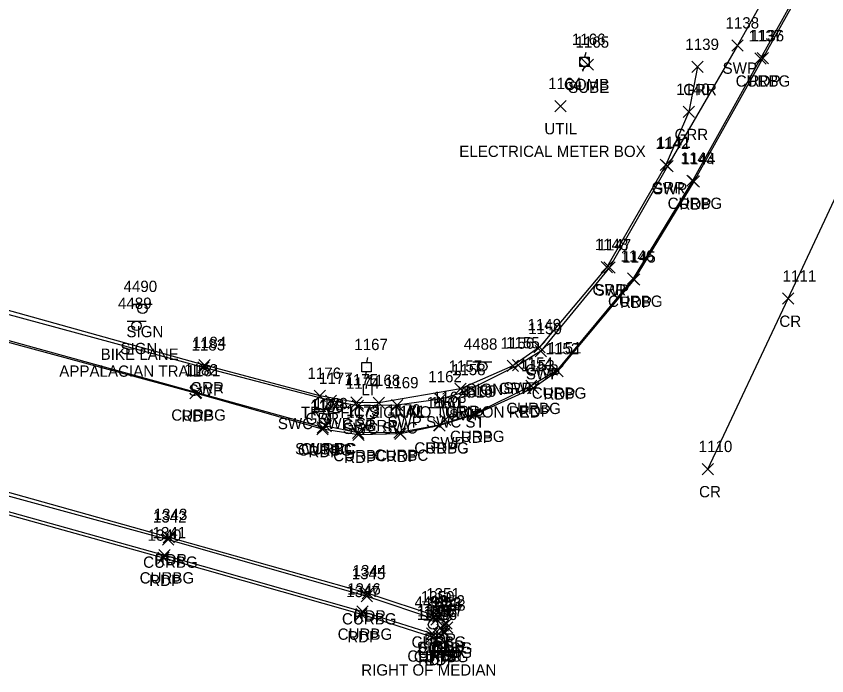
# Model space of a CAD drawing. Extents: x 1690689 to 1696275, y 438760 to 444007.
# Drawn here: x 1692953 to 1693096.4, y 438844.6 to 438961.2 of the extents above; entities that cross this region are included whole.
import ezdxf

# ---------------------------------------------------------------- set-up
doc = ezdxf.new("R2010")
doc.units = 0
for name, color, linetype in [('P_A', 7, 'Continuous'), ('P_I', 7, 'Continuous'), ('P_TIC', 7, 'Continuous'), ('PET', 7, 'Continuous'), ('PRC', 7, 'Continuous'), ('R_A', 7, 'Continuous'), ('R_I', 7, 'Continuous'), ('R_TIC', 7, 'Continuous'), ('RC', 7, 'Continuous'), ('RGR', 7, 'Continuous'), ('RSW', 7, 'Continuous'), ('S_A', 7, 'Continuous'), ('S_C', 7, 'Continuous'), ('S_I', 7, 'Continuous'), ('SSGN', 7, 'Continuous'), ('U_A', 7, 'Continuous'), ('U_C', 7, 'Continuous'), ('U_I', 7, 'Continuous'), ('U_TIC', 7, 'Continuous'), ('UDEFAULT', 7, 'Continuous'), ('ULP', 7, 'Continuous'), ('UP', 7, 'Continuous')]:
    doc.layers.add(name, color=color, linetype=linetype)

msp = doc.modelspace()

# ---------------------------------------------------------------- linework, layer by layer
at = {"layer": 'P_TIC'}
for points in [[(1693084.1, 438952.79), (1693086.1, 438954.79)], [(1693086.1, 438952.79), (1693084.1, 438954.79)], [(1693071.88, 438931.02), (1693073.88, 438933.02)], [(1693073.88, 438931.02), (1693071.88, 438933.02)], [(1693061.34, 438913.66), (1693063.34, 438915.66)], [(1693063.34, 438913.66), (1693061.34, 438915.66)], [(1693088.6, 438910.3), (1693090.6, 438912.3)], [(1693090.6, 438910.3), (1693088.6, 438912.3)], [(1693047.8, 438897.45), (1693049.8, 438899.45)], [(1693049.8, 438897.45), (1693047.8, 438899.45)], [(1693043.46, 438894.45), (1693045.46, 438896.45)], [(1693045.46, 438894.45), (1693043.46, 438896.45)], [(1692983.73, 438893.57), (1692985.73, 438895.57)], [(1692985.73, 438893.57), (1692983.73, 438895.57)], [(1693033.2, 438889.8), (1693035.2, 438891.8)], [(1693035.2, 438889.8), (1693033.2, 438891.8)], [(1693006.21, 438887.24), (1693008.21, 438889.24)], [(1693008.21, 438887.24), (1693006.21, 438889.24)], [(1693026.9, 438887.88), (1693028.9, 438889.88)], [(1693028.9, 438887.88), (1693026.9, 438889.88)], [(1693012.55, 438886.23), (1693014.55, 438888.23)], [(1693014.55, 438886.23), (1693012.55, 438888.23)], [(1693019.98, 438886.4), (1693021.98, 438888.4)], [(1693021.98, 438886.4), (1693019.98, 438888.4)], [(1693074.4, 438880.17), (1693076.4, 438882.17)], [(1693076.4, 438880.17), (1693074.4, 438882.17)], [(1692979.03, 438868.15), (1692981.03, 438870.15)], [(1692981.03, 438868.15), (1692979.03, 438870.15)], [(1692978.05, 438864.49), (1692980.05, 438866.49)], [(1692980.05, 438864.49), (1692978.05, 438866.49)], [(1693014.23, 438858.21), (1693016.23, 438860.21)], [(1693016.23, 438858.21), (1693014.23, 438860.21)], [(1693013.1, 438854.52), (1693015.1, 438856.52)], [(1693015.1, 438854.52), (1693013.1, 438856.52)], [(1693026.67, 438854.11), (1693028.67, 438856.11)], [(1693028.67, 438854.11), (1693026.67, 438856.11)], [(1693028.13, 438852.87), (1693030.13, 438854.87)], [(1693030.13, 438852.87), (1693028.13, 438854.87)], [(1693028.26, 438852.13), (1693030.26, 438854.13)], [(1693030.26, 438852.13), (1693028.26, 438854.13)], [(1693028.26, 438852.13), (1693030.26, 438854.13)], [(1693030.26, 438852.13), (1693028.26, 438854.13)], [(1693027.79, 438851.15), (1693029.79, 438853.15)], [(1693029.79, 438851.15), (1693027.79, 438853.15)], [(1693025.61, 438850.49), (1693027.61, 438852.49)], [(1693027.61, 438850.49), (1693025.61, 438852.49)], [(1693026.81, 438850.47), (1693028.81, 438852.47)], [(1693028.81, 438850.47), (1693026.81, 438852.47)]]:
    msp.add_lwpolyline(points, dxfattribs=at)
at = {"layer": 'PET'}
for points in [[(1693125.8, 439077.7), (1693116.74, 439032.37), (1693117.43, 439025.65), (1693115.9, 439015.71), (1693111.21, 439002.42), (1693106.01, 438991.1), (1693085.1, 438953.79), (1693072.88, 438932.02), (1693062.34, 438914.66), (1693048.8, 438898.45), (1693044.46, 438895.45), (1693034.2, 438890.8), (1693027.9, 438888.88), (1693020.98, 438887.4), (1693013.55, 438887.23), (1693007.21, 438888.24), (1692984.73, 438894.57), (1692943.33, 438905.8), (1692898.33, 438918.08), (1692858.37, 438928.85), (1692835.39, 438935.21), (1692797.06, 438945.81)], [(1692767.64, 438925.55), (1692788.12, 438920.87), (1692810.81, 438915.2), (1692847.49, 438905.73), (1692889.57, 438894.03), (1692933.46, 438882.17), (1692980.03, 438869.15), (1693015.23, 438859.21), (1693027.67, 438855.11), (1693029.13, 438853.87), (1693029.26, 438853.13)], [(1692765.95, 438921.86), (1692787.57, 438917.51), (1692810.13, 438912.04), (1692846.3, 438902.13), (1692888.63, 438890.39), (1692931.95, 438878.57), (1692979.05, 438865.49), (1693014.1, 438855.52), (1693026.61, 438851.49), (1693027.81, 438851.47), (1693028.79, 438852.15), (1693029.26, 438853.13)]]:
    msp.add_lwpolyline(points, dxfattribs=at)
at = {"layer": 'PRC'}
msp.add_lwpolyline([(1693075.4, 438881.17), (1693089.6, 438911.3), (1693103.78, 438941.64), (1693117.42, 438973.77), (1693128.92, 439005.9), (1693137.63, 439039.04), (1693143.37, 439073.85)], dxfattribs=at)
at = {"layer": 'R_TIC'}
for points in [[(1693079.63, 438955.05), (1693081.63, 438957.05)], [(1693081.63, 438955.05), (1693079.63, 438957.05)], [(1693083.72, 438952.77), (1693085.72, 438954.77)], [(1693085.72, 438952.77), (1693083.72, 438954.77)], [(1693072.53, 438951.26), (1693074.53, 438953.26)], [(1693074.53, 438951.26), (1693072.53, 438953.26)], [(1693071, 438943.32), (1693073, 438945.32)], [(1693073, 438943.32), (1693071, 438945.32)], [(1693066.94, 438933.93), (1693068.94, 438935.93)], [(1693068.94, 438933.93), (1693066.94, 438935.93)], [(1693067.27, 438933.74), (1693069.27, 438935.74)], [(1693069.27, 438933.74), (1693067.27, 438935.74)], [(1693071.69, 438931.15), (1693073.69, 438933.15)], [(1693073.69, 438931.15), (1693071.69, 438933.15)], [(1693056.5, 438915.87), (1693058.5, 438917.87)], [(1693058.5, 438915.87), (1693056.5, 438917.87)], [(1693057, 438915.81), (1693059, 438917.81)], [(1693059, 438915.81), (1693057, 438917.81)], [(1693061.14, 438913.84), (1693063.14, 438915.84)], [(1693063.14, 438913.84), (1693061.14, 438915.84)], [(1693044.6, 438901.71), (1693046.6, 438903.71)], [(1693046.6, 438901.71), (1693044.6, 438903.71)], [(1693044.81, 438901.02), (1693046.81, 438903.02)], [(1693046.81, 438901.02), (1693044.81, 438903.02)], [(1692985.15, 438898.12), (1692987.15, 438900.12)], [(1692987.15, 438898.12), (1692985.15, 438900.12)], [(1692985.35, 438898.55), (1692987.35, 438900.55)], [(1692987.35, 438898.55), (1692985.35, 438900.55)], [(1693039.89, 438898.43), (1693041.89, 438900.43)], [(1693041.89, 438898.43), (1693039.89, 438900.43)], [(1693040.81, 438898.51), (1693042.81, 438900.51)], [(1693042.81, 438898.51), (1693040.81, 438900.51)], [(1693047.64, 438897.6), (1693049.64, 438899.6)], [(1693049.64, 438897.6), (1693047.64, 438899.6)], [(1692983.87, 438893.72), (1692985.87, 438895.72)], [(1692985.87, 438893.72), (1692983.87, 438895.72)], [(1693030.63, 438894.36), (1693032.63, 438896.36)], [(1693032.63, 438894.36), (1693030.63, 438896.36)], [(1693031.24, 438893.76), (1693033.24, 438895.76)], [(1693033.24, 438893.76), (1693031.24, 438895.76)], [(1693043.15, 438894.89), (1693045.15, 438896.89)], [(1693045.15, 438894.89), (1693043.15, 438896.89)], [(1693005.72, 438893.11), (1693007.72, 438895.11)], [(1693007.72, 438893.11), (1693005.72, 438895.11)], [(1693007.71, 438892.22), (1693009.71, 438894.22)], [(1693009.71, 438892.22), (1693007.71, 438894.22)], [(1693007.71, 438892.22), (1693009.71, 438894.22)], [(1693009.71, 438892.22), (1693007.71, 438894.22)], [(1693027.09, 438892.51), (1693029.09, 438894.51)], [(1693029.09, 438892.51), (1693027.09, 438894.51)], [(1693027.09, 438892.51), (1693029.09, 438894.51)], [(1693029.09, 438892.51), (1693027.09, 438894.51)], [(1693012.23, 438891.96), (1693014.23, 438893.96)], [(1693014.23, 438891.96), (1693012.23, 438893.96)], [(1693012.47, 438891.36), (1693014.47, 438893.36)], [(1693014.47, 438891.36), (1693012.47, 438893.36)], [(1693016.18, 438891.86), (1693018.18, 438893.86)], [(1693018.18, 438891.86), (1693016.18, 438893.86)], [(1693019.42, 438891.44), (1693021.42, 438893.44)], [(1693021.42, 438891.44), (1693019.42, 438893.44)], [(1693033.18, 438889.95), (1693035.18, 438891.95)], [(1693035.18, 438889.95), (1693033.18, 438891.95)], [(1693026.86, 438887.9), (1693028.86, 438889.9)], [(1693028.86, 438887.9), (1693026.86, 438889.9)], [(1693026.86, 438887.9), (1693028.86, 438889.9)], [(1693028.86, 438887.9), (1693026.86, 438889.9)], [(1693027.9, 438888.85), (1693029.9, 438890.85)], [(1693029.9, 438888.85), (1693027.9, 438890.85)], [(1693006.26, 438887.54), (1693008.26, 438889.54)], [(1693008.26, 438887.54), (1693006.26, 438889.54)], [(1693006.82, 438887.75), (1693008.82, 438889.75)], [(1693008.82, 438887.75), (1693006.82, 438889.75)], [(1693006.82, 438887.75), (1693008.82, 438889.75)], [(1693008.82, 438887.75), (1693006.82, 438889.75)], [(1693012.52, 438886.55), (1693014.52, 438888.55)], [(1693014.52, 438886.55), (1693012.52, 438888.55)], [(1693019.82, 438886.62), (1693021.82, 438888.62)], [(1693021.82, 438886.62), (1693019.82, 438888.62)], [(1692978.89, 438867.71), (1692980.89, 438869.71)], [(1692980.89, 438867.71), (1692978.89, 438869.71)], [(1692978.27, 438864.93), (1692980.27, 438866.93)], [(1692980.27, 438864.93), (1692978.27, 438866.93)], [(1693014.06, 438857.69), (1693016.06, 438859.69)], [(1693016.06, 438857.69), (1693014.06, 438859.69)], [(1693013.3, 438854.98), (1693015.3, 438856.98)], [(1693015.3, 438854.98), (1693013.3, 438856.98)], [(1693026.38, 438853.59), (1693028.38, 438855.59)], [(1693028.38, 438853.59), (1693026.38, 438855.59)], [(1693027.5, 438852.53), (1693029.5, 438854.53)], [(1693029.5, 438852.53), (1693027.5, 438854.53)], [(1693025.63, 438851.11), (1693027.63, 438853.11)], [(1693027.63, 438851.11), (1693025.63, 438853.11)], [(1693026.78, 438851.01), (1693028.78, 438853.01)], [(1693028.78, 438851.01), (1693026.78, 438853.01)], [(1693026.78, 438851.01), (1693028.78, 438853.01)], [(1693028.78, 438851.01), (1693026.78, 438853.01)], [(1693027.46, 438851.76), (1693029.46, 438853.76)], [(1693029.46, 438851.76), (1693027.46, 438853.76)]]:
    msp.add_lwpolyline(points, dxfattribs=at)
at = {"layer": 'RC'}
for points in [[(1693116.74, 439032.37), (1693117.22, 439025.72), (1693115.72, 439016.6), (1693110.92, 439002.56), (1693105.62, 438991.28), (1693084.72, 438953.77), (1693072.69, 438932.15), (1693062.14, 438914.84), (1693048.64, 438898.6), (1693044.15, 438895.89), (1693034.18, 438890.95), (1693027.86, 438888.9)], [(1693007.26, 438888.54), (1692984.87, 438894.72), (1692943.42, 438906.13), (1692898.49, 438918.23), (1692858.65, 438929.27), (1692835.33, 438935.51), (1692797.49, 438945.86), (1692745.37, 438957.23), (1692684.06, 438970.13), (1692664.88, 438974.8), (1692632.07, 438981.54), (1692605.04, 438987.41), (1692554.61, 438997.65), (1692506.45, 439007.89), (1692458.66, 439018.07), (1692409.83, 439028.32)], [(1692767.42, 438924.95), (1692788.17, 438920.39), (1692810.74, 438914.88), (1692847.4, 438905.21), (1692889.57, 438893.51), (1692933.14, 438881.44), (1692979.89, 438868.71), (1693015.06, 438858.69), (1693027.38, 438854.59), (1693028.5, 438853.53), (1693028.46, 438852.76), (1693027.78, 438852.01)], [(1692766.36, 438922.45), (1692787.63, 438917.87), (1692810.3, 438912.33), (1692846.5, 438902.75), (1692888.78, 438890.91), (1692932.11, 438879.07), (1692979.27, 438865.93), (1693014.3, 438855.98), (1693026.63, 438852.11), (1693027.78, 438852.01)], [(1693027.86, 438888.9), (1693020.82, 438887.62), (1693013.52, 438887.55), (1693007.82, 438888.75)]]:
    msp.add_lwpolyline(points, dxfattribs=at)
at = {"layer": 'RGR'}
msp.add_lwpolyline([(1693073.53, 438952.26), (1693072, 438944.32), (1693067.94, 438934.93), (1693057.5, 438916.87), (1693045.6, 438902.71), (1693040.89, 438899.43), (1693031.63, 438895.36), (1693017.18, 438892.86), (1693013.23, 438892.96), (1693006.72, 438894.11), (1692986.35, 438899.55), (1692944.65, 438911.14), (1692896.92, 438924.75), (1692860.53, 438933.88), (1692836.58, 438940.74), (1692798.54, 438951.07), (1692780.52, 438955.46)], dxfattribs=at)
at = {"layer": 'RSW'}
for points in [[(1693112.55, 439041.91), (1693112.03, 439025.46), (1693111.25, 439017.93), (1693106.5, 439004.15), (1693101.66, 438993.53), (1693080.63, 438956.05), (1693068.27, 438934.74), (1693058, 438916.81), (1693045.81, 438902.02), (1693041.81, 438899.51), (1693032.24, 438894.76), (1693028.09, 438893.51), (1693028.9, 438889.85)], [(1693008.71, 438893.22), (1692986.15, 438899.12), (1692944.72, 438910.3), (1692899.76, 438922.66), (1692860.92, 438933.26), (1692836.71, 438940.07), (1692798.61, 438950.76), (1692797.49, 438945.86)], [(1693028.09, 438893.51), (1693020.42, 438892.44), (1693013.47, 438892.36), (1693008.71, 438893.22), (1693007.82, 438888.75)]]:
    msp.add_lwpolyline(points, dxfattribs=at)
at = {"layer": 'SSGN'}
for p, q in [((1692973.72, 438910.33), (1692977.06, 438910.33)), ((1692975.37, 438909.49), (1692975.37, 438909.49)), ((1692972.66, 438907.34), (1692975.99, 438907.34)), ((1692974.3, 438906.5), (1692974.3, 438906.5)), ((1693033.83, 438900.12), (1693037.17, 438900.12)), ((1693035.48, 438899.29), (1693035.48, 438899.29)), ((1693025.11, 438854.5), (1693028.44, 438854.5)), ((1693026.76, 438853.67), (1693026.76, 438853.67))]:
    msp.add_line(p, q, dxfattribs=at)
for centre in [(1692975.37, 438909.49), (1692974.3, 438906.5), (1693035.48, 438899.29), (1693026.76, 438853.67)]:
    msp.add_circle(centre, 0.833, dxfattribs=at)
at = {"layer": 'U_TIC'}
for points in [[(1693053.13, 438951.66), (1693055.13, 438953.66)], [(1693055.13, 438951.66), (1693053.13, 438953.66)]]:
    msp.add_lwpolyline(points, dxfattribs=at)
at = {"layer": 'UDEFAULT'}
for points in [[(1693048.29, 438944.34), (1693050.29, 438946.34)], [(1693050.29, 438944.34), (1693048.29, 438946.34)]]:
    msp.add_lwpolyline(points, dxfattribs=at)
at = {"layer": 'ULP'}
for p, q in [((1693014.17, 438898.37), (1693014.17, 438900.03)), ((1693014.17, 438900.03), (1693015.84, 438900.03)), ((1693015.17, 438900.87), (1693015, 438900.03)), ((1693015.84, 438900.03), (1693015.84, 438898.37)), ((1693015, 438899.2), (1693015, 438899.2)), ((1693015.84, 438898.37), (1693014.17, 438898.37)), ((1693014.75, 438897.53), (1693015, 438898.37))]:
    msp.add_line(p, q, dxfattribs=at)
at = {"layer": 'UP'}
for p, q in [((1693053.79, 438954.82), (1693053.54, 438953.99)), ((1693052.71, 438952.32), (1693052.71, 438953.99)), ((1693052.71, 438953.99), (1693054.38, 438953.99)), ((1693053.54, 438953.15), (1693053.54, 438953.15)), ((1693054.38, 438953.99), (1693054.38, 438952.32)), ((1693054.38, 438952.32), (1693052.71, 438952.32)), ((1693053.29, 438951.49), (1693053.54, 438952.32))]:
    msp.add_line(p, q, dxfattribs=at)
msp.add_circle((1693053.54, 438953.15), 0.833, dxfattribs=at)

# ---------------------------------------------------------------- texts
at = {"layer": 'P_A'}
for s, p in [('RDP', (1693082.59, 438948.79)), ('RDP', (1693070.36, 438927.02)), ('RDP', (1693059.83, 438909.66)), ('CR', (1693088.03, 438906.3)), ('RDP', (1693046.29, 438893.45)), ('RDP', (1692982.22, 438889.57)), ('RDP', (1693041.95, 438890.45)), ('RDP', (1693031.69, 438885.8)), ('RDP', (1693025.39, 438883.88)), ('RDP', (1693004.7, 438883.24)), ('RDP', (1693011.04, 438882.23)), ('RDP', (1693018.47, 438882.4)), ('CR', (1693073.83, 438876.17)), ('RDP', (1692977.52, 438864.15)), ('RDP', (1692976.54, 438860.49)), ('RDP', (1693012.71, 438854.21)), ('RDP', (1693011.59, 438850.52)), ('RDP', (1693025.16, 438850.11)), ('RDP', (1693026.62, 438848.87)), ('RDP', (1693026.75, 438848.13)), ('RDP', (1693026.75, 438848.13)), ('RDP', (1693024.09, 438846.49)), ('RDP', (1693025.3, 438846.47)), ('RDP', (1693026.28, 438847.15))]:
    msp.add_text(s, height=2, dxfattribs=at).set_placement(p)
at = {"layer": 'P_I'}
for s, p in [('1136', (1693082.92, 438956.79)), ('1144', (1693070.75, 438935.02)), ('1145', (1693060.21, 438917.66)), ('1111', (1693088.61, 438914.3)), ('1152', (1693046.68, 438901.45)), ('1153', (1693042.33, 438898.45)), ('1181', (1692983.17, 438897.57)), ('4610', (1693031.37, 438893.8)), ('1180', (1693005, 438891.24)), ('1161', (1693026.29, 438891.88)), ('1172', (1693011.42, 438890.23)), ('1171', (1693019.42, 438890.4)), ('1110', (1693073.76, 438884.17)), ('1343', (1692977.34, 438872.15)), ('1340', (1692976.27, 438868.49)), ('1344', (1693012.53, 438862.21)), ('1347', (1693011.41, 438858.52)), ('1351', (1693025.55, 438858.11)), ('1352', (1693026.44, 438856.87)), ('1357', (1693026.1, 438855.15)), ('1358', (1693026.57, 438856.13)), ('1358', (1693026.57, 438856.13)), ('1348', (1693023.91, 438854.49)), ('1356', (1693025.06, 438854.47))]:
    msp.add_text(s, height=2, dxfattribs=at).set_placement(p)
at = {"layer": 'R_A'}
for s, p in [('SWP', (1693077.99, 438951.05)), ('CURBG', (1693080.31, 438948.77)), ('GRR', (1693071.02, 438947.26)), ('GRR', (1693069.49, 438939.32)), ('GRR', (1693065.43, 438929.93)), ('SWP', (1693065.63, 438929.74)), ('CURBG', (1693068.27, 438927.15)), ('GRR', (1693054.98, 438911.87)), ('SWP', (1693055.36, 438911.81)), ('CURBG', (1693057.72, 438909.84)), ('GRR', (1693043.09, 438897.71)), ('SWP', (1693043.18, 438897.02)), ('SWP', (1692983.52, 438894.12)), ('GRR', (1692983.83, 438894.55)), ('GRR', (1693038.38, 438894.43)), ('SWP', (1693039.18, 438894.51)), ('CURBG', (1693044.22, 438893.6)), ('CURBG', (1693039.73, 438890.89)), ('CURBG', (1692980.45, 438889.72)), ('GRR', (1693029.12, 438890.36)), ('SWP', (1693029.6, 438889.76)), ('SWC SWP ST', (1692999.3, 438888.22)), ('SWC SWP ST', (1692999.3, 438888.22)), ('GRR', (1693004.21, 438889.11)), ('GRR', (1693010.72, 438887.96)), ('GRR', (1693014.66, 438887.86)), ('SWP SWC ST', (1693018.68, 438888.51)), ('SWP SWC ST', (1693018.68, 438888.51)), ('SWC', (1693010.83, 438887.36)), ('SWC', (1693017.78, 438887.44)), ('CURBG', (1693029.76, 438885.95)), ('SWC CC', (1693002.35, 438883.75)), ('CURBC', (1693003.4, 438883.75)), ('CURBG', (1693023.45, 438883.9)), ('CURBC', (1693023.45, 438883.9)), ('SWP', (1693026.26, 438884.85)), ('CURBG', (1693002.84, 438883.54)), ('CURBC', (1693009.1, 438882.55)), ('CURBC', (1693016.4, 438882.62)), ('CURBG', (1692975.47, 438863.71)), ('CURBG', (1692974.85, 438860.93)), ('CURBG', (1693010.65, 438853.69)), ('CURBG', (1693009.89, 438850.98)), ('CURBG', (1693022.96, 438849.59)), ('CURBG', (1693024.04, 438847.76)), ('CURBG', (1693024.09, 438848.53)), ('CURBG', (1693022.22, 438847.11)), ('CURBG', (1693023.37, 438847.01)), ('CURBG', (1693023.37, 438847.01))]:
    msp.add_text(s, height=2, dxfattribs=at).set_placement(p)
at = {"layer": 'R_I'}
for s, p in [('1138', (1693078.5, 438959.05)), ('1137', (1693082.6, 438956.77)), ('1139', (1693071.4, 438955.26)), ('1140', (1693069.79, 438947.32)), ('1142', (1693066.14, 438937.74)), ('1141', (1693066.38, 438937.93)), ('1143', (1693070.57, 438935.15)), ('1148', (1693055.37, 438919.87)), ('1147', (1693055.87, 438919.81)), ('1146', (1693059.95, 438917.84)), ('1149', (1693043.47, 438905.71)), ('1150', (1693043.6, 438905.02)), ('1184', (1692984.22, 438902.55)), ('1156', (1693038.71, 438902.43)), ('1155', (1693039.69, 438902.51)), ('1183', (1692984.03, 438902.12)), ('1151', (1693047.08, 438901.6)), ('1157', (1693029.5, 438898.36)), ('1154', (1693042.02, 438898.89)), ('1182', (1692982.74, 438897.72)), ('1176', (1693004.54, 438897.11)), ('1162', (1693025.92, 438896.51)), ('1162', (1693025.92, 438896.51)), ('1158', (1693030.11, 438897.76)), ('1177', (1693006.58, 438896.22)), ('1177', (1693006.58, 438896.22)), ('1175', (1693011.11, 438895.96)), ('1174', (1693011.35, 438895.36)), ('1168', (1693015, 438895.86)), ('1169', (1693018.24, 438895.44)), ('1159', (1693032.04, 438893.95)), ('1163', (1693026.72, 438892.85)), ('1179', (1693005.12, 438891.54)), ('1178', (1693005.7, 438891.75)), ('1178', (1693005.7, 438891.75)), ('1160', (1693025.6, 438891.9)), ('1160', (1693025.6, 438891.9)), ('1173', (1693011.39, 438890.55)), ('1170', (1693018.61, 438890.62)), ('1342', (1692977.2, 438871.71)), ('1341', (1692977.14, 438868.93)), ('1345', (1693012.37, 438861.69)), ('1346', (1693011.56, 438858.98)), ('1350', (1693024.6, 438857.59)), ('1353', (1693025.81, 438856.53)), ('1349', (1693023.93, 438855.11)), ('1355', (1693025.09, 438855.01)), ('1355', (1693025.09, 438855.01)), ('1354', (1693025.76, 438855.76))]:
    msp.add_text(s, height=2, dxfattribs=at).set_placement(p)
at = {"layer": 'S_A'}
for p in [(1692972.51, 438904.47), (1692971.44, 438901.48), (1693032.62, 438894.27), (1693023.89, 438848.65)]:
    msp.add_text('SIGN', height=2, dxfattribs=at).set_placement(p)
at = {"layer": 'S_C'}
for s, p in [('BIKE LANE', (1692967.95, 438900.47)), ('APPALACIAN TRAIL', (1692960.63, 438897.48)), ('NO TURN ON RED', (1693022.46, 438890.27)), ('RIGHT OF MEDIAN', (1693014.05, 438844.65))]:
    msp.add_text(s, height=2, dxfattribs=at).set_placement(p)
at = {"layer": 'S_I'}
for s, p in [('4490', (1692972, 438912.47)), ('4489', (1692971.02, 438909.48)), ('4488', (1693032.2, 438902.27)), ('4498', (1693023.48, 438856.65))]:
    msp.add_text(s, height=2, dxfattribs=at).set_placement(p)
at = {"layer": 'U_A'}
for s, p in [('COMB', (1693049.93, 438948.15)), ('SUBE', (1693050.67, 438947.66)), ('UTIL', (1693046.45, 438940.34)), ('LI', (1693014.1, 438894.2))]:
    msp.add_text(s, height=2, dxfattribs=at).set_placement(p)
at = {"layer": 'U_C'}
for s, p in [('ELECTRICAL METER BOX', (1693031.4, 438936.34)), ('TRAFFIC SIGNAL', (1693003.38, 438890.2))]:
    msp.add_text(s, height=2, dxfattribs=at).set_placement(p)
at = {"layer": 'U_I'}
for s, p in [('1166', (1693051.32, 438956.15)), ('1165', (1693051.96, 438955.66)), ('1164', (1693047.12, 438948.34)), ('1167', (1693012.83, 438902.2))]:
    msp.add_text(s, height=2, dxfattribs=at).set_placement(p)

doc.saveas('drawing.dxf')
